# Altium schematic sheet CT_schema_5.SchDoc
size 294 x 169 mm
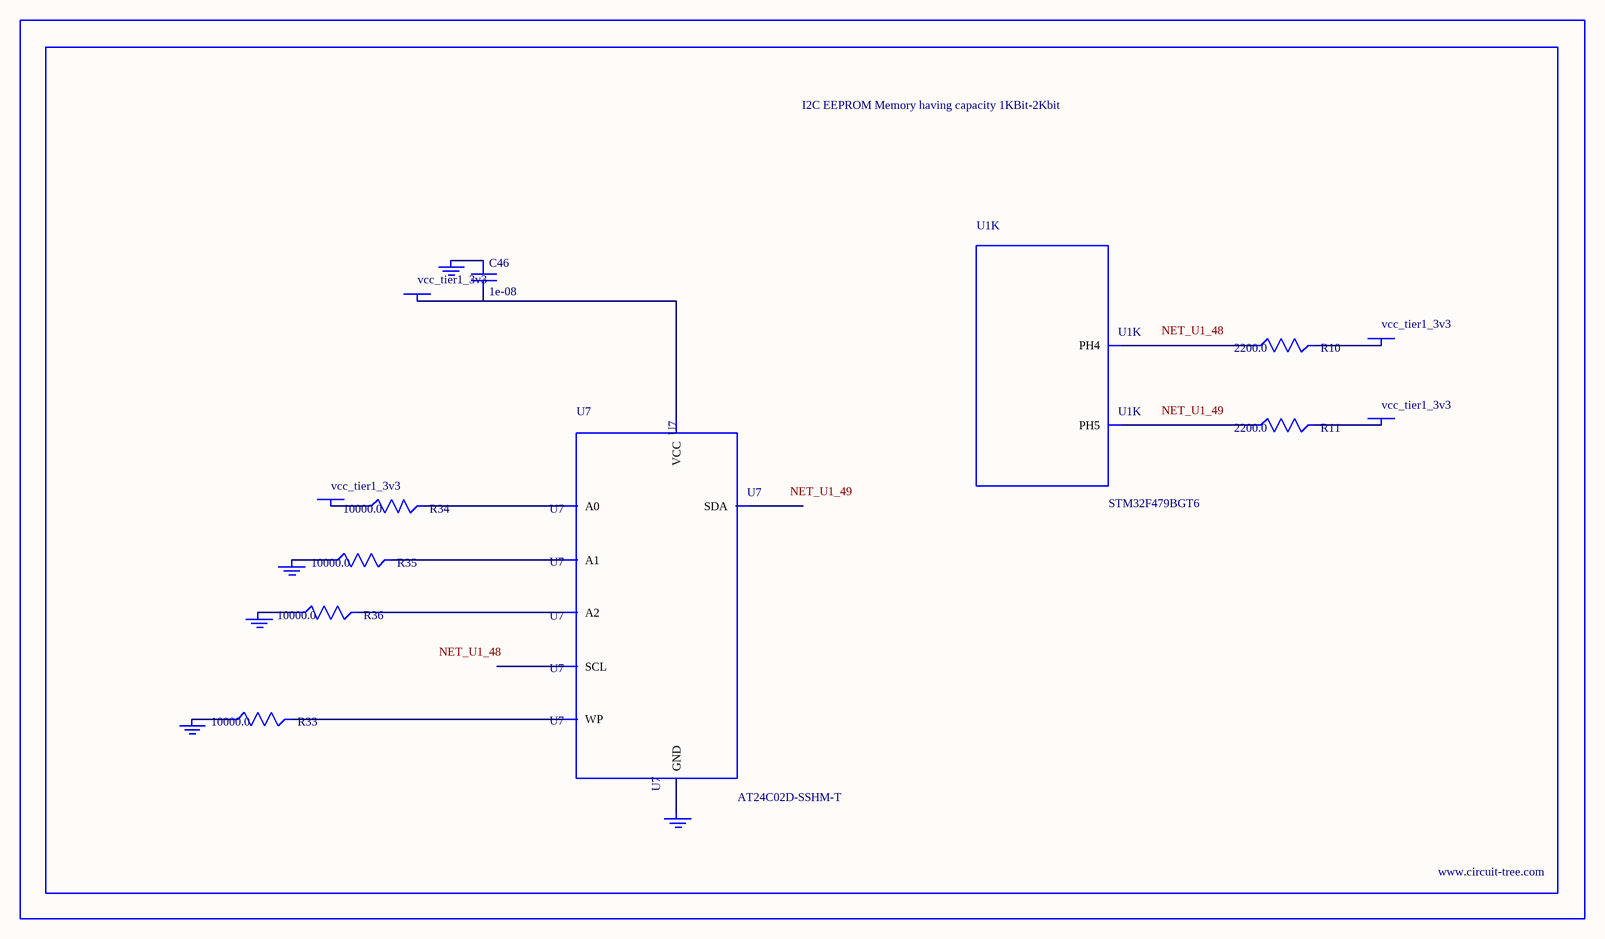
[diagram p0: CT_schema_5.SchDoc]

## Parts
BORDER4  (no value)
C46  1e-08  [C0402]
GND_INSTANCE_4_0  (no value)
GND_INSTANCE_4_1  (no value)
GND_INSTANCE_4_2  (no value)
GND_INSTANCE_4_3  (no value)
GND_INSTANCE_4_4  (no value)
POWER_INSTANCE_4_0  vcc_tier1_3v3
POWER_INSTANCE_4_1  vcc_tier1_3v3
POWER_INSTANCE_4_2  vcc_tier1_3v3
POWER_INSTANCE_4_3  vcc_tier1_3v3
R10  2200.0  [R0603]
R11  2200.0  [R0603]
R33  10000.0  [R0603]
R34  10000.0  [R0603]
R35  10000.0  [R0603]
R36  10000.0  [R0603]
U1  STM32F479BGT6  [LQFP208]  (part K of 16)
U7  AT24C02D-SSHM-T  [AT24C02D]

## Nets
NetC46_1: C46.1 GND_INSTANCE_4_3.0(GND)
NetC46_2: C46.2 POWER_INSTANCE_4_1.0(PWR) U7.8(VCC)
NetGND_INSTANCE_4_0_0: GND_INSTANCE_4_0.0(GND) R35.1
NetGND_INSTANCE_4_1_0: GND_INSTANCE_4_1.0(GND) R36.1
NetGND_INSTANCE_4_2_0: GND_INSTANCE_4_2.0(GND) R33.1
NetGND_INSTANCE_4_4_0: GND_INSTANCE_4_4.0(GND) U7.4(GND)
NetPOWER_INSTANCE_4_0_0: POWER_INSTANCE_4_0.0(PWR) R34.1
NetPOWER_INSTANCE_4_2_0: POWER_INSTANCE_4_2.0(PWR) R10.2
NetPOWER_INSTANCE_4_3_0: POWER_INSTANCE_4_3.0(PWR) R11.2
NetR10_1: R10.1 U1.48(PH4)
NetR11_1: R11.1 U1.49(PH5)
NetR33_2: R33.2 U7.7(WP)
NetR34_2: R34.2 U7.1(A0)
NetR35_2: R35.2 U7.2(A1)
NetR36_2: R36.2 U7.3(A2)

Not connected (* = marked no-connect by the designer): U7 5(SDA) 6(SCL)

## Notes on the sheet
- Labels drawn without touching a wire or pin: NET_U1_48, NET_U1_49

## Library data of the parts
BORDER4 = BORDER_PAGE4
C46 = C0402C103K3RAC
GND_INSTANCE_4_0-GND_INSTANCE_4_4 = GND
POWER_INSTANCE_4_0-POWER_INSTANCE_4_3 = PWR
R10 R11 = RC0603JR-072K2L
R33-R36 = RC0603JR-0710KL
